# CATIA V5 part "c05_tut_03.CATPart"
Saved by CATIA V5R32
Part number: Part1
Bounding box of the stored display mesh (mm): x -75 to 75, y -150 to 150, z 39 to 189
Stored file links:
  D:\PROJECTS\Project 2022\CATIA V5 6R 2022\Resources\Tutorial Files\c05_catia_v5_6r2022_tut\c05_tut_03.CATPart
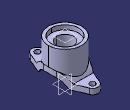
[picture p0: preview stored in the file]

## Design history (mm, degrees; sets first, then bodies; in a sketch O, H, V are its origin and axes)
Body1 (main body)
  Sketch1 on yz-plane, origin (0, 0, 0), H (0, 1, 0), V (0, 0, 1)
    arc A1 centre (0, 0) radius 105 from (83.2406, 64) to (-83.2406, 64) ccw
    arc A2 centre (0, 0) radius 80 from (69.8498, 39) to (-69.8498, 39) ccw
    line L1 (69.8498, 39) -> (150, 39)
    line L2 (150, 39) -> (150, 64)
    line L3 (150, 64) -> (83.2406, 64)
    point P5 (-83.2406, 64)
    line L4 (-83.2406, 64) -> (-150, 64)
    line L5 (-150, 64) -> (-150, 39)
    point P7 (-150, 39)
    line L6 (-150, 39) -> (-69.8498, 39)
    radius A1 = 105
    radius A2 = 80
    distance L3 L1 = 25
    distance H L1 = 39
    distance V L5 = 150
    horizontal: L1 H, L3 H, L4 H, L6 H
    vertical: L2 V, L5 V
    coincidence: P5 L3, P7 L1
    symmetry: L5 L2 V
  Pad1: profile Sketch1, direction (1, 0, 0), length 75, mirrored extent
  Sketch2 on xy-plane, origin (0, 0, 0), H (1, 0, 0), V (0, 1, 0)
    arc A1 centre (0, 0) radius 75 from (-68.7386, 30) to (-68.7386, -30) ccw
    arc A2 centre (0, 125) radius 25 from (22.9129, 135) to (-22.9129, 135) ccw
    point P1 (0, 125)
    point P2 (0, 150)
    arc A3 centre (0, -125) radius 25 from (-22.9129, -135) to (22.9129, -135) ccw
    point P3 (0, -125)
    reference projected line E1 (-75, 150) -> (75, 150) from edge [face of Pad1 from Sketch1.L3 | face of Pad1 from Sketch1.L2]
    reference projected line E2 (-75, -150) -> (75, -150) from edge [face of Pad1 from Sketch1.L5 | face of Pad1 from Sketch1.L4]
    reference projected line E3 (75, 83.2406) -> (75, -83.2406) from edge [face of Pad1 from Sketch1.A1 | end face of Pad1]
    line L1 (22.9129, 135) -> (68.7386, 30)
    line L2 (-22.9129, 135) -> (-68.7386, 30)
    line L3 (-22.9129, -135) -> (-68.7386, -30)
    line L4 (22.9129, -135) -> (68.7386, -30)
    point P11 (68.7386, -30)
    arc A4 centre (0, 0) radius 75 from (68.7386, -30) to (68.7386, 30) ccw
    radius A2 = 25
    coincidence: P1 V, A2 P2, P2 V, P3 V, A1 P11, A1 A4
    tangency: A2 E1, A3 E2, A1 E3, L1 A2, L1 A1, L2 A2, L2 A1, L3 A3, L3 A1, L4 A3, L4 A1
    symmetry: A2 A3 H
  Pocket1: profile Sketch2, direction (0, 0, 1), through (limit type 3), outer side
  Plane1: type Offset, RefPlane xy-plane, Offset 189
  Sketch3 on Plane1, origin (0, 0, 189), H (1, 0, 0), V (0, 1, 0)
    circle A1 centre (0, 0) radius 75
    reference projected arc E1 centre (0, 0) radius 75 from (68.7386, -30) to (68.7386, 30) ccw from edge [face of Pad1 from Sketch1.A1 | face of Pocket1]
    radius A1 = 75
    concentricity: A1 E1
  Pad2: profile Sketch3, direction (0, 0, 1), up to face of Pad1 from Sketch1.A1
  Sketch4 on yz-plane, origin (0, 0, 0), H (0, 1, 0), V (0, 0, 1)
    point P1 (0, 39)
    line L1 (0, 39) -> (0, 189)
    line L2 (0, 189) -> (61.5, 189)
    line L3 (61.5, 189) -> (61.5, 169)
    line L4 (61.5, 169) -> (37.5, 169)
    line L5 (37.5, 169) -> (37.5, 39)
    line L6 (37.5, 39) -> (0, 39)
    reference projected line E1 (-75, 189) -> (75, 189) from edge [face of Pad2 from Sketch3.A1 | start face of Pad2]
    axis line L7 (0, 189) -> (0, 254.467)
    reference projected line E2 (135, 39) -> (69.8498, 39) from edge [face of Pocket1 from Sketch2.L1 | face of Pad1 from Sketch1.L1]
    distance L2 L4 = 20
    radius about axis L5 L7 = 37.5
    radius about axis L7 L3 = 61.5
    coincidence: P1 V, L2 E1, L6 E2
    vertical: L1 V, L3 V, L5 V, L7 V
    horizontal: L2 H, L4 H, L6 H
  Groove1: profile Sketch4, axis Sketch4.L7, angle 360
  Sketch5 on face of Pad1 from Sketch1.L3, origin (0, 0, 64), H (1, 0, 0), V (0, 1, 0)
    circle A1 centre (0, 125) radius 12.5
    point P1 (0, 125)
    circle A2 centre (0, -125) radius 12.5
    point P2 (0, -125)
    reference projected arc E1 centre (0, 125) radius 25 from (22.9129, 135) to (-22.9129, 135) ccw from edge [face of Pocket1 | face of Pad1 from Sketch1.L3]
    reference projected arc E2 centre (0, -125) radius 25 from (-22.9129, -135) to (22.9129, -135) ccw from edge [face of Pocket1 | face of Pad1 from Sketch1.L4]
    radius A1 = 12.5
    coincidence: P1 V, P2 V
    concentricity: A1 E1, A2 E2
    equal size: A1 A2
  Pocket2: profile Sketch5, direction (0, 0, -1), through (limit type 3)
